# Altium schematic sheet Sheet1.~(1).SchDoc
size A; SheetNumber: 1; SheetTotal: 1
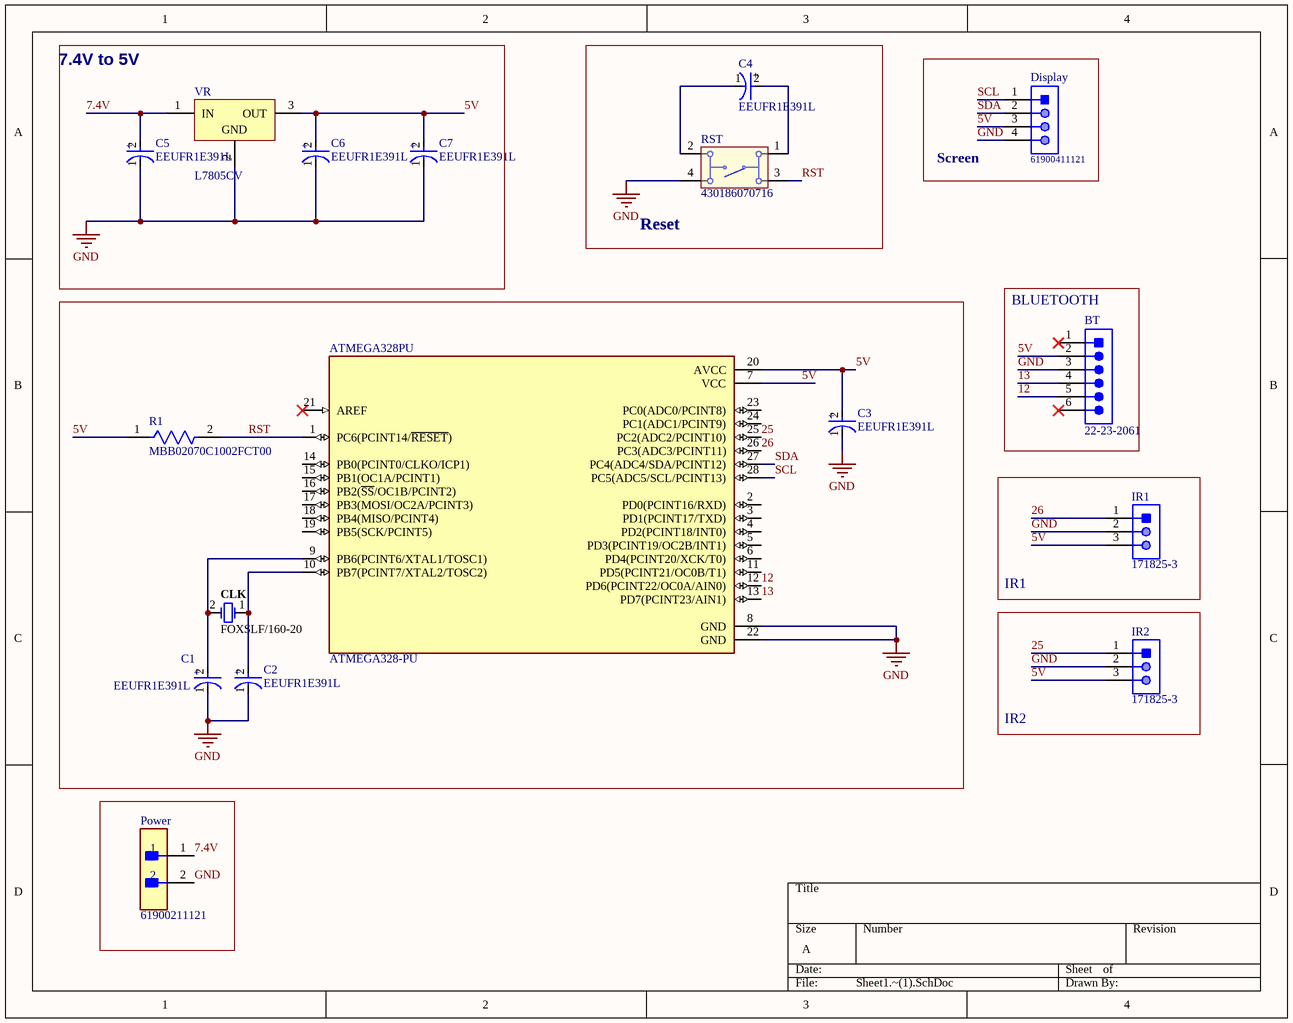
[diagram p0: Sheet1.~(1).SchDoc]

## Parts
ATMEGA328PU  ATMEGA328-PU  [DIP787W46P254L3467H508Q28]
BT  22-23-2061  [MOLX-22-23-2061_V]
C1  EEUFR1E391L  [FP-RAD-TH-D_8_0_5-L_15_1-MFG]
C2  EEUFR1E391L  [FP-RAD-TH-D_8_0_5-L_15_1-MFG]
C3  EEUFR1E391L  [FP-RAD-TH-D_8_0_5-L_15_1-MFG]
C4  EEUFR1E391L  [FP-RAD-TH-D_8_0_5-L_15_1-MFG]
C5  EEUFR1E391L  [FP-RAD-TH-D_8_0_5-L_15_1-MFG]
C6  EEUFR1E391L  [FP-RAD-TH-D_8_0_5-L_15_1-MFG]
C7  EEUFR1E391L  [FP-RAD-TH-D_8_0_5-L_15_1-MFG]
CLK  FOXSLF/160-20  [FOX-FOXSLF160-20]
Display  61900411121  [61900411121]
IR1  171825-3  [TECO-171825-3_V]
IR2  171825-3  [TECO-171825-3_V]
Power  61900211121  [FP-61900211121-MFG]
R1  MBB02070C1002FCT00  [FP-MBB0207-MFG]
RST  430186070716  [430186070716]
VR  L7805CV  [TO220]

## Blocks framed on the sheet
7.4V to 5V: C5-C7 VR
Reset: C4 RST
Screen: Display
BLUETOOTH: BT
IR1: IR1
IR2: IR2

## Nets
GND: ATMEGA328PU.8(GND) ATMEGA328PU.22(GND) BT.3 C1.1(C) C2.1(C) C3.1(C) C5.1(C) C6.1(C) C7.1(C) Display.4 IR1.2 IR2.2 Power.2 RST.4 VR.2(GND)
5V: ATMEGA328PU.7(VCC) ATMEGA328PU.20(AVCC) BT.2 C3.2(A) C6.2(A) C7.2(A) Display.3 IR1.3 IR2.3 R1.1 VR.3(OUT)  [also labelled ~{}]
7.4V: C5.2(A) Power.1 VR.1(IN)
12: ATMEGA328PU.12(PD6(PCINT22/OC0A/AIN0)) BT.5
13: ATMEGA328PU.13(PD7(PCINT23/AIN1)) BT.4
25: ATMEGA328PU.25(PC2(ADC2/PCINT10)) IR2.1
26: ATMEGA328PU.26(PC3(ADC3/PCINT11)) IR1.1
RST: ATMEGA328PU.1(PC6(PCINT14/~{RESET})) R1.2 RST.3
SCL: ATMEGA328PU.28(PC5(ADC5/SCL/PCINT13)) Display.1
SDA: ATMEGA328PU.27(PC4(ADC4/SDA/PCINT12)) Display.2
NetATMEGA328PU_9: ATMEGA328PU.9(PB6(PCINT6/XTAL1/TOSC1)) C1.2(A) CLK.2
NetATMEGA328PU_10: ATMEGA328PU.10(PB7(PCINT7/XTAL2/TOSC2)) C2.2(A) CLK.1
NetC4_1: C4.1(C) RST.2
NetC4_2: C4.2(A) RST.1

Not connected (* = marked no-connect by the designer): ATMEGA328PU 2(PD0(PCINT16/RXD)) 3(PD1(PCINT17/TXD)) 4(PD2(PCINT18/INT0)) 5(PD3(PCINT19/OC2B/INT1)) 6(PD4(PCINT20/XCK/T0)) 11(PD5(PCINT21/OC0B/T1)) 14(PB0(PCINT0/CLKO/ICP1)) 15(PB1(OC1A/PCINT1)) 16(PB2(~{SS}/OC1B/PCINT2)) 17(PB3(MOSI/OC2A/PCINT3)) 18(PB4(MISO/PCINT4)) 19(PB5(SCK/PCINT5)) 21(AREF)* 23(PC0(ADC0/PCINT8)) 24(PC1(ADC1/PCINT9)); BT 1* 6*

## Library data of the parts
ATMEGA328PU = ATMEGA328-PU: AVR AVRÂ® ATmega Microcontroller IC 8-Bit 20MHz 32KB (16K x 16) FLASH 28-PDIP; MF: Microchip
BT = CMP-2000-05536-1: Male Header, Pitch 2.54 mm, 1 x 6 Position, Height 10.67 mm, Tail Length 3.56 mm, 0 to 70 degC, RoHS, Bulk; Manufacturer: Molex; Pitch: 2.54mm; Mounting Angle: Vertical; Current Rating: 4A; Number of Positions / Contacts: 6; Voltage Rating: 250V
C1-C7 = CMP-05427-000460-1: Aluminum Electrolytic Capacitors (Radial Lead Type) 390uF ±20% 25V; Impedance: 41mR; Lead Diameter: 0.6mm; Ripple Current (AC): 1.24A; Life (Hours): 8000Hour; Dielectric Material: Aluminium
CLK = CMP-1749-00003-1: Resistance Weld Thru-Hole Crystal, 16 MHz, -20 to 70 degC, 2-Pin THD, RoHS, Bulk; Voltage Rating: 250 V; Tolerance: 1%; Resistance: 221 kohm; Case\Package: Axial; Power Rating: 250 mW
Display = CMP-1502-00586-1: Male Locking Header WR-WTB, THT, Vertical, pitch 2.54 mm, 1 x 4 position; Manufacturer: Wurth Elektronik; Working Voltage: 250VAC; Pitch: 2.54mm; Contact Resistance: 20mOhm; Position: 1x4
IR1 IR2 = CMP-2000-07494-1: Male Header, Pitch 2.5 mm, 1 x 3 Position, Height 10.4 mm, Tail Length 3.6 mm, / -20 to 95 degC / , RoHS, Bulk; Manufacturer: TE Connectivity; Mating Alignment: Yes(With); Tail Length: 0.142inch; Mating Post Length: 7.5mm; PCB Thickness: 0.063inch; PCB Mount Alignment: No(Without); Voltage Rating: 350V; Max Voltage Rating (AC): 250V; Plating Thickness: 0.8um; PCB Mounting Orientation: Vertical; Number of Positions: 3; PCB Mount Retention: Without; Max Current Rating: 3.5A; Max Voltage Rating (DC): 350.25kV; Pitch: 2.5mm; Approvals: UL; Contact Resistance: 20mOhm
Power = CMP-1502-00584-2: CONN HEADER VERT 2POS 2.54MM; Number of Contacts: 2; Gender: Male; Current Rating: 3A; Voltage Rating: 250V; Insulation Resistance: 1GR
R1 = CMP-02408-000035-1: RES 10K OHM 0.6W 1% AXIAL; Voltage Rating: 300V; Resistance: 10kR; Max Power Dissipation: 600mW; Temperature Coefficient: 50ppm/°C
RST = CMP-1453-00013-1: WS-TATV THT Tact Switch 6X6 mm; Manufacturer: Wuerth Elektronik; NoPins: 04
VR = CMP-0244-00483-1: Positive Voltage Regulator, 5V, 3-Pin TO-220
